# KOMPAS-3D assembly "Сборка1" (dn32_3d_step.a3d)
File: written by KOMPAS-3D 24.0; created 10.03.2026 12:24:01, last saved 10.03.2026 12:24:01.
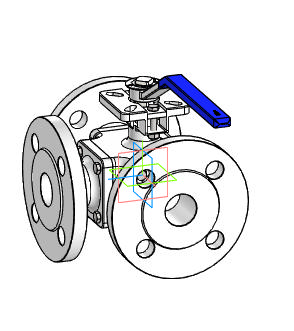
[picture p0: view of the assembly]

Document properties: Автор: R2D2; Полное имя файла: E:\Работа\Зайцев\BV3232P(4pc)-FP-3WL-F-ISO-H Кран шаровой DN.ru Ду15-100 Ру16\DN32\исходные материалы\dn32_3d_step.a3d

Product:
- Component [detail]: Деталь  | qty 1  | Автор: R2D2; source file: Деталь Деталь.m3d
- Component [detail]: Деталь1  | qty 1  | Автор: R2D2; source file: Деталь1 Деталь1.m3d
- Component [detail]: AS 1110 - M6 x 30  | qty 1  | Автор: R2D2; source file: AS 1110 - M6 x 30 AS 1110 - M6 x 30.m3d
- Component [detail]: AS 1110 - M6 x 30  | qty 1  | Комментарий: Болты и винты   шестигранные точные   метрические ISO; Автор: R2D2; additional columns: Сталь, мягкая; source file: AS 1110 - M6 x 30 AS 1110 - M6 x 30.m3d
- Component [detail]: ANSI B18.2.4.2M - M6x1 - 10  | designation ANSI B18.2.4.2M - M6x1  | qty 1  | Автор: R2D2; source file: ANSI B18.2.4.2M - M6x1 ANSI B18.2.4.2M - M6x1 - 10.m3d
- Component [detail]: ANSI B18.2.4.2M - M6x1 - 10  | designation ANSI B18.2.4.2M - M6x1  | qty 1  | Комментарий: Типы метрических   шестигранных гаек   2; Автор: R2D2; additional columns: Сталь, мягкая; source file: ANSI B18.2.4.2M - M6x1 ANSI B18.2.4.2M - M6x1 - 10.m3d
- Component [detail]: AS 1110 - M6 x 12  | qty 1  | Автор: R2D2; source file: AS 1110 - M6 x 12 AS 1110 - M6 x 12.m3d
- Component [detail]: AS 1110 - M6 x 12  | qty 11  | Комментарий: Болты и винты   шестигранные точные   метрические ISO; Автор: R2D2; additional columns: Сталь, мягкая; source file: AS 1110 - M6 x 12 AS 1110 - M6 x 12.m3d
- Part/product: Сборка1

Referenced files in E:\Работа\Зайцев\BV3232P(4pc)-FP-3WL-F-ISO-H Кран шаровой DN.ru Ду15-100 Ру16\DN32\исходные материалы\: Деталь Деталь.m3d, Деталь1 Деталь1.m3d, AS 1110 - M6 x 30 AS 1110 - M6 x 30.m3d, ANSI B18.2.4.2M - M6x1 ANSI B18.2.4.2M - M6x1 - 10.m3d, AS 1110 - M6 x 12 AS 1110 - M6 x 12.m3d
